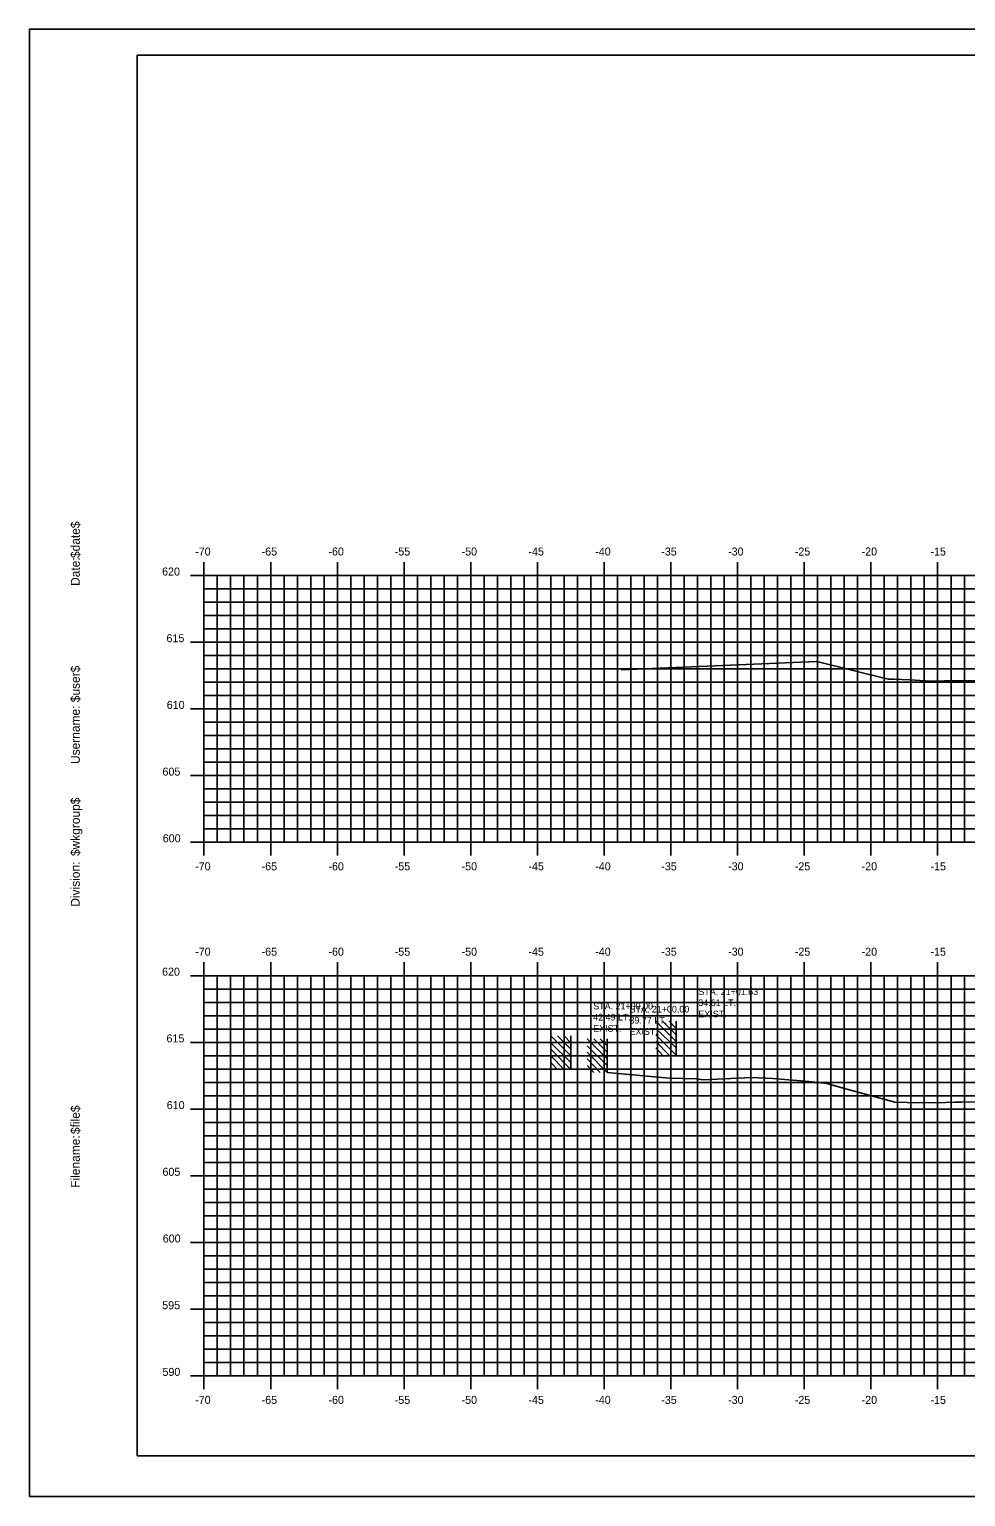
# Model space of a CAD drawing. Extents: x 1048806 to 1048976, y 780904 to 781014.
# Drawn here: x 1048805.9 to 1048876.1, y 780904.1 to 781014.1 of the extents above; entities that cross this region are included whole.
import ezdxf

# ---------------------------------------------------------------- set-up
doc = ezdxf.new("R2010")
doc.units = 0
for name, color, linetype in [('D_Text_Monospaced', 7, 'Continuous'), ('Default', 7, 'Continuous'), ('H_V ANNOTATION', 7, 'Continuous'), ('MAJOR', 7, 'Continuous'), ('MINOR', 7, 'Continuous'), ('S_Buildings', 7, 'Continuous'), ('S_Buildings_SillElevation', 7, 'Continuous'), ('S_Roadway_Centerline', 7, 'Continuous')]:
    doc.layers.add(name, color=color, linetype=linetype)

msp = doc.modelspace()

# ---------------------------------------------------------------- linework, layer by layer
at = {"layer": 'Default'}
for p, q in [((1048973.98, 781012.11), (1048813.98, 781012.11)), ((1048813.98, 781012.11), (1048813.98, 780907.11)), ((1048813.98, 780907.11), (1048973.98, 780907.11))]:
    msp.add_line(p, q, dxfattribs=at)
msp.add_lwpolyline([(1048805.89, 780904.06), (1048975.89, 780904.06), (1048975.89, 781014.06), (1048805.89, 781014.06)], close=True, dxfattribs=at)
at = {"layer": 'MAJOR'}
for p, q in [((1048818.98, 780974.12), (1048818.98, 780973.11)), ((1048823.98, 780974.12), (1048823.98, 780973.11)), ((1048828.98, 780974.12), (1048828.98, 780973.11)), ((1048833.98, 780974.12), (1048833.98, 780973.11)), ((1048838.98, 780974.12), (1048838.98, 780973.11)), ((1048843.98, 780974.12), (1048843.98, 780973.11)), ((1048848.98, 780974.12), (1048848.98, 780973.11)), ((1048853.98, 780974.12), (1048853.98, 780973.11)), ((1048858.98, 780974.12), (1048858.98, 780973.11)), ((1048863.98, 780974.12), (1048863.98, 780973.11)), ((1048868.98, 780974.12), (1048868.98, 780973.11)), ((1048873.98, 780974.12), (1048873.98, 780973.11)), ((1048817.98, 780973.11), (1048818.98, 780973.11)), ((1048818.98, 780973.11), (1048958.98, 780973.11)), ((1048818.98, 780953.11), (1048818.98, 780973.11)), ((1048818.98, 780953.11), (1048818.98, 780973.11)), ((1048818.98, 780973.11), (1048958.98, 780973.11)), ((1048823.98, 780953.11), (1048823.98, 780973.11)), ((1048828.98, 780953.11), (1048828.98, 780973.11)), ((1048833.98, 780953.11), (1048833.98, 780973.11)), ((1048838.98, 780953.11), (1048838.98, 780973.11)), ((1048843.98, 780953.11), (1048843.98, 780973.11)), ((1048848.98, 780953.11), (1048848.98, 780973.11)), ((1048853.98, 780953.11), (1048853.98, 780973.11)), ((1048858.98, 780953.11), (1048858.98, 780973.11)), ((1048863.98, 780953.11), (1048863.98, 780973.11)), ((1048868.98, 780953.11), (1048868.98, 780973.11)), ((1048873.98, 780953.11), (1048873.98, 780973.11)), ((1048817.98, 780968.11), (1048818.98, 780968.11)), ((1048818.98, 780968.11), (1048958.98, 780968.11)), ((1048817.98, 780963.11), (1048818.98, 780963.11)), ((1048818.98, 780963.11), (1048958.98, 780963.11)), ((1048817.98, 780958.11), (1048818.98, 780958.11)), ((1048818.98, 780958.11), (1048958.98, 780958.11)), ((1048817.98, 780953.11), (1048818.98, 780953.11)), ((1048818.98, 780953.11), (1048958.98, 780953.11)), ((1048818.98, 780953.11), (1048958.98, 780953.11)), ((1048818.98, 780952.11), (1048818.98, 780953.11)), ((1048823.98, 780952.11), (1048823.98, 780953.11)), ((1048828.98, 780952.11), (1048828.98, 780953.11)), ((1048833.98, 780952.11), (1048833.98, 780953.11)), ((1048838.98, 780952.11), (1048838.98, 780953.11)), ((1048843.98, 780952.11), (1048843.98, 780953.11)), ((1048848.98, 780952.11), (1048848.98, 780953.11)), ((1048853.98, 780952.11), (1048853.98, 780953.11)), ((1048858.98, 780952.11), (1048858.98, 780953.11)), ((1048863.98, 780952.11), (1048863.98, 780953.11)), ((1048868.98, 780952.11), (1048868.98, 780953.11)), ((1048873.98, 780952.11), (1048873.98, 780953.11)), ((1048818.98, 780944.12), (1048818.98, 780943.11)), ((1048823.98, 780944.12), (1048823.98, 780943.11)), ((1048828.98, 780944.12), (1048828.98, 780943.11)), ((1048833.98, 780944.12), (1048833.98, 780943.11)), ((1048838.98, 780944.12), (1048838.98, 780943.11)), ((1048843.98, 780944.12), (1048843.98, 780943.11)), ((1048848.98, 780944.12), (1048848.98, 780943.11)), ((1048853.98, 780944.12), (1048853.98, 780943.11)), ((1048858.98, 780944.12), (1048858.98, 780943.11)), ((1048863.98, 780944.12), (1048863.98, 780943.11)), ((1048868.98, 780944.12), (1048868.98, 780943.11)), ((1048873.98, 780944.12), (1048873.98, 780943.11)), ((1048817.98, 780943.11), (1048818.98, 780943.11)), ((1048818.98, 780943.11), (1048958.98, 780943.11)), ((1048818.98, 780913.11), (1048818.98, 780943.11)), ((1048818.98, 780913.11), (1048818.98, 780943.11)), ((1048818.98, 780943.11), (1048958.98, 780943.11)), ((1048823.98, 780913.11), (1048823.98, 780943.11)), ((1048828.98, 780913.11), (1048828.98, 780943.11)), ((1048833.98, 780913.11), (1048833.98, 780943.11)), ((1048838.98, 780913.11), (1048838.98, 780943.11)), ((1048843.98, 780913.11), (1048843.98, 780943.11)), ((1048848.98, 780913.11), (1048848.98, 780943.11)), ((1048853.98, 780913.11), (1048853.98, 780943.11)), ((1048858.98, 780913.11), (1048858.98, 780943.11)), ((1048863.98, 780913.11), (1048863.98, 780943.11)), ((1048868.98, 780913.11), (1048868.98, 780943.11)), ((1048873.98, 780913.11), (1048873.98, 780943.11)), ((1048817.98, 780938.11), (1048818.98, 780938.11)), ((1048818.98, 780938.11), (1048958.98, 780938.11)), ((1048817.98, 780933.11), (1048818.98, 780933.11)), ((1048818.98, 780933.11), (1048958.98, 780933.11)), ((1048817.98, 780928.11), (1048818.98, 780928.11)), ((1048818.98, 780928.11), (1048958.98, 780928.11)), ((1048817.98, 780923.11), (1048818.98, 780923.11)), ((1048818.98, 780923.11), (1048958.98, 780923.11)), ((1048817.98, 780918.11), (1048818.98, 780918.11)), ((1048818.98, 780918.11), (1048958.98, 780918.11)), ((1048817.98, 780913.11), (1048818.98, 780913.11)), ((1048818.98, 780913.11), (1048958.98, 780913.11)), ((1048818.98, 780913.11), (1048958.98, 780913.11)), ((1048818.98, 780912.11), (1048818.98, 780913.11)), ((1048823.98, 780912.11), (1048823.98, 780913.11)), ((1048828.98, 780912.11), (1048828.98, 780913.11)), ((1048833.98, 780912.11), (1048833.98, 780913.11)), ((1048838.98, 780912.11), (1048838.98, 780913.11)), ((1048843.98, 780912.11), (1048843.98, 780913.11)), ((1048848.98, 780912.11), (1048848.98, 780913.11)), ((1048853.98, 780912.11), (1048853.98, 780913.11)), ((1048858.98, 780912.11), (1048858.98, 780913.11)), ((1048863.98, 780912.11), (1048863.98, 780913.11)), ((1048868.98, 780912.11), (1048868.98, 780913.11)), ((1048873.98, 780912.11), (1048873.98, 780913.11))]:
    msp.add_line(p, q, dxfattribs=at)
at = {"layer": 'MINOR'}
for p, q in [((1048819.98, 780953.11), (1048819.98, 780973.11)), ((1048820.98, 780953.11), (1048820.98, 780973.11)), ((1048821.98, 780953.11), (1048821.98, 780973.11)), ((1048822.98, 780953.11), (1048822.98, 780973.11)), ((1048824.98, 780953.11), (1048824.98, 780973.11)), ((1048825.98, 780953.11), (1048825.98, 780973.11)), ((1048826.98, 780953.11), (1048826.98, 780973.11)), ((1048827.98, 780953.11), (1048827.98, 780973.11)), ((1048829.98, 780953.11), (1048829.98, 780973.11)), ((1048830.98, 780953.11), (1048830.98, 780973.11)), ((1048831.98, 780953.11), (1048831.98, 780973.11)), ((1048832.98, 780953.11), (1048832.98, 780973.11)), ((1048834.98, 780953.11), (1048834.98, 780973.11)), ((1048835.98, 780953.11), (1048835.98, 780973.11)), ((1048836.98, 780953.11), (1048836.98, 780973.11)), ((1048837.98, 780953.11), (1048837.98, 780973.11)), ((1048839.98, 780953.11), (1048839.98, 780973.11)), ((1048840.98, 780953.11), (1048840.98, 780973.11)), ((1048841.98, 780953.11), (1048841.98, 780973.11)), ((1048842.98, 780953.11), (1048842.98, 780973.11)), ((1048844.98, 780953.11), (1048844.98, 780973.11)), ((1048845.98, 780953.11), (1048845.98, 780973.11)), ((1048846.98, 780953.11), (1048846.98, 780973.11)), ((1048847.98, 780953.11), (1048847.98, 780973.11)), ((1048849.98, 780953.11), (1048849.98, 780973.11)), ((1048850.98, 780953.11), (1048850.98, 780973.11)), ((1048851.98, 780953.11), (1048851.98, 780973.11)), ((1048852.98, 780953.11), (1048852.98, 780973.11)), ((1048854.98, 780953.11), (1048854.98, 780973.11)), ((1048855.98, 780953.11), (1048855.98, 780973.11)), ((1048856.98, 780953.11), (1048856.98, 780973.11)), ((1048857.98, 780953.11), (1048857.98, 780973.11)), ((1048859.98, 780953.11), (1048859.98, 780973.11)), ((1048860.98, 780953.11), (1048860.98, 780973.11)), ((1048861.98, 780953.11), (1048861.98, 780973.11)), ((1048862.98, 780953.11), (1048862.98, 780973.11)), ((1048864.98, 780953.11), (1048864.98, 780973.11)), ((1048865.98, 780953.11), (1048865.98, 780973.11)), ((1048866.98, 780953.11), (1048866.98, 780973.11)), ((1048867.98, 780953.11), (1048867.98, 780973.11)), ((1048869.98, 780953.11), (1048869.98, 780973.11)), ((1048870.98, 780953.11), (1048870.98, 780973.11)), ((1048871.98, 780953.11), (1048871.98, 780973.11)), ((1048872.98, 780953.11), (1048872.98, 780973.11)), ((1048874.98, 780953.11), (1048874.98, 780973.11)), ((1048875.98, 780953.11), (1048875.98, 780973.11)), ((1048818.98, 780972.11), (1048958.98, 780972.11)), ((1048818.98, 780972.11), (1048819.98, 780972.11)), ((1048818.98, 780971.11), (1048958.98, 780971.11)), ((1048818.98, 780971.11), (1048819.98, 780971.11)), ((1048818.98, 780970.11), (1048958.98, 780970.11)), ((1048818.98, 780970.11), (1048819.98, 780970.11)), ((1048818.98, 780969.11), (1048958.98, 780969.11)), ((1048818.98, 780969.11), (1048819.98, 780969.11)), ((1048818.98, 780967.11), (1048958.98, 780967.11)), ((1048818.98, 780967.11), (1048819.98, 780967.11)), ((1048818.98, 780966.11), (1048958.98, 780966.11)), ((1048818.98, 780966.11), (1048819.98, 780966.11)), ((1048818.98, 780965.11), (1048958.98, 780965.11)), ((1048818.98, 780965.11), (1048819.98, 780965.11)), ((1048818.98, 780964.11), (1048958.98, 780964.11)), ((1048818.98, 780964.11), (1048819.98, 780964.11)), ((1048818.98, 780962.11), (1048958.98, 780962.11)), ((1048818.98, 780962.11), (1048819.98, 780962.11)), ((1048818.98, 780961.11), (1048958.98, 780961.11)), ((1048818.98, 780961.11), (1048819.98, 780961.11)), ((1048818.98, 780960.11), (1048958.98, 780960.11)), ((1048818.98, 780960.11), (1048819.98, 780960.11)), ((1048818.98, 780959.11), (1048958.98, 780959.11)), ((1048818.98, 780959.11), (1048819.98, 780959.11)), ((1048818.98, 780957.11), (1048958.98, 780957.11)), ((1048818.98, 780957.11), (1048819.98, 780957.11)), ((1048818.98, 780956.11), (1048958.98, 780956.11)), ((1048818.98, 780956.11), (1048819.98, 780956.11)), ((1048818.98, 780955.11), (1048958.98, 780955.11)), ((1048818.98, 780955.11), (1048819.98, 780955.11)), ((1048818.98, 780954.11), (1048958.98, 780954.11)), ((1048818.98, 780954.11), (1048819.98, 780954.11)), ((1048819.98, 780913.11), (1048819.98, 780943.11)), ((1048820.98, 780913.11), (1048820.98, 780943.11)), ((1048821.98, 780913.11), (1048821.98, 780943.11)), ((1048822.98, 780913.11), (1048822.98, 780943.11)), ((1048824.98, 780913.11), (1048824.98, 780943.11)), ((1048825.98, 780913.11), (1048825.98, 780943.11)), ((1048826.98, 780913.11), (1048826.98, 780943.11)), ((1048827.98, 780913.11), (1048827.98, 780943.11)), ((1048829.98, 780913.11), (1048829.98, 780943.11)), ((1048830.98, 780913.11), (1048830.98, 780943.11)), ((1048831.98, 780913.11), (1048831.98, 780943.11)), ((1048832.98, 780913.11), (1048832.98, 780943.11)), ((1048834.98, 780913.11), (1048834.98, 780943.11)), ((1048835.98, 780913.11), (1048835.98, 780943.11)), ((1048836.98, 780913.11), (1048836.98, 780943.11)), ((1048837.98, 780913.11), (1048837.98, 780943.11)), ((1048839.98, 780913.11), (1048839.98, 780943.11)), ((1048840.98, 780913.11), (1048840.98, 780943.11)), ((1048841.98, 780913.11), (1048841.98, 780943.11)), ((1048842.98, 780913.11), (1048842.98, 780943.11)), ((1048844.98, 780913.11), (1048844.98, 780943.11)), ((1048845.98, 780913.11), (1048845.98, 780943.11)), ((1048846.98, 780913.11), (1048846.98, 780943.11)), ((1048847.98, 780913.11), (1048847.98, 780943.11)), ((1048849.98, 780913.11), (1048849.98, 780943.11)), ((1048850.98, 780913.11), (1048850.98, 780943.11)), ((1048851.98, 780913.11), (1048851.98, 780943.11)), ((1048852.98, 780913.11), (1048852.98, 780943.11)), ((1048854.98, 780913.11), (1048854.98, 780943.11)), ((1048855.98, 780913.11), (1048855.98, 780943.11)), ((1048856.98, 780913.11), (1048856.98, 780943.11)), ((1048857.98, 780913.11), (1048857.98, 780943.11)), ((1048859.98, 780913.11), (1048859.98, 780943.11)), ((1048860.98, 780913.11), (1048860.98, 780943.11)), ((1048861.98, 780913.11), (1048861.98, 780943.11)), ((1048862.98, 780913.11), (1048862.98, 780943.11)), ((1048864.98, 780913.11), (1048864.98, 780943.11)), ((1048865.98, 780913.11), (1048865.98, 780943.11)), ((1048866.98, 780913.11), (1048866.98, 780943.11)), ((1048867.98, 780913.11), (1048867.98, 780943.11)), ((1048869.98, 780913.11), (1048869.98, 780943.11)), ((1048870.98, 780913.11), (1048870.98, 780943.11)), ((1048871.98, 780913.11), (1048871.98, 780943.11)), ((1048872.98, 780913.11), (1048872.98, 780943.11)), ((1048874.98, 780913.11), (1048874.98, 780943.11)), ((1048875.98, 780913.11), (1048875.98, 780943.11)), ((1048818.98, 780942.11), (1048958.98, 780942.11)), ((1048818.98, 780942.11), (1048819.98, 780942.11)), ((1048818.98, 780941.11), (1048958.98, 780941.11)), ((1048818.98, 780941.11), (1048819.98, 780941.11)), ((1048818.98, 780940.11), (1048958.98, 780940.11)), ((1048818.98, 780940.11), (1048819.98, 780940.11)), ((1048818.98, 780939.11), (1048958.98, 780939.11)), ((1048818.98, 780939.11), (1048819.98, 780939.11)), ((1048818.98, 780937.11), (1048958.98, 780937.11)), ((1048818.98, 780937.11), (1048819.98, 780937.11)), ((1048818.98, 780936.11), (1048958.98, 780936.11)), ((1048818.98, 780936.11), (1048819.98, 780936.11)), ((1048818.98, 780935.11), (1048958.98, 780935.11)), ((1048818.98, 780935.11), (1048819.98, 780935.11)), ((1048818.98, 780934.11), (1048958.98, 780934.11)), ((1048818.98, 780934.11), (1048819.98, 780934.11)), ((1048818.98, 780932.11), (1048958.98, 780932.11)), ((1048818.98, 780932.11), (1048819.98, 780932.11)), ((1048818.98, 780931.11), (1048958.98, 780931.11)), ((1048818.98, 780931.11), (1048819.98, 780931.11)), ((1048818.98, 780930.11), (1048958.98, 780930.11)), ((1048818.98, 780930.11), (1048819.98, 780930.11)), ((1048818.98, 780929.11), (1048958.98, 780929.11)), ((1048818.98, 780929.11), (1048819.98, 780929.11)), ((1048818.98, 780927.11), (1048958.98, 780927.11)), ((1048818.98, 780927.11), (1048819.98, 780927.11)), ((1048818.98, 780926.11), (1048958.98, 780926.11)), ((1048818.98, 780926.11), (1048819.98, 780926.11)), ((1048818.98, 780925.11), (1048958.98, 780925.11)), ((1048818.98, 780925.11), (1048819.98, 780925.11)), ((1048818.98, 780924.11), (1048958.98, 780924.11)), ((1048818.98, 780924.11), (1048819.98, 780924.11)), ((1048818.98, 780922.11), (1048958.98, 780922.11)), ((1048818.98, 780922.11), (1048819.98, 780922.11)), ((1048818.98, 780921.11), (1048958.98, 780921.11)), ((1048818.98, 780921.11), (1048819.98, 780921.11)), ((1048818.98, 780920.11), (1048958.98, 780920.11)), ((1048818.98, 780920.11), (1048819.98, 780920.11)), ((1048818.98, 780919.11), (1048958.98, 780919.11)), ((1048818.98, 780919.11), (1048819.98, 780919.11)), ((1048818.98, 780917.11), (1048958.98, 780917.11)), ((1048818.98, 780917.11), (1048819.98, 780917.11)), ((1048818.98, 780916.11), (1048958.98, 780916.11)), ((1048818.98, 780916.11), (1048819.98, 780916.11)), ((1048818.98, 780915.11), (1048958.98, 780915.11)), ((1048818.98, 780915.11), (1048819.98, 780915.11)), ((1048818.98, 780914.11), (1048958.98, 780914.11)), ((1048818.98, 780914.11), (1048819.98, 780914.11))]:
    msp.add_line(p, q, dxfattribs=at)
at = {"layer": 'S_Buildings'}
for p, q in [((1048846.49, 780937.1), (1048844.98, 780938.61)), ((1048846.49, 780937.59), (1048845.48, 780938.61)), ((1048846.49, 780938.08), (1048845.97, 780938.61)), ((1048846.49, 780936.08), (1048846.49, 780938.61)), ((1048846.49, 780936.61), (1048844.98, 780938.08)), ((1048846.49, 780936.08), (1048844.98, 780937.59)), ((1048849.21, 780936.87), (1048847.71, 780938.38)), ((1048849.21, 780936.38), (1048847.71, 780937.86)), ((1048849.21, 780935.86), (1048847.71, 780937.37)), ((1048849.21, 780937.37), (1048848.2, 780938.38)), ((1048849.21, 780937.86), (1048848.69, 780938.38)), ((1048849.21, 780935.86), (1048849.21, 780938.38)), ((1048845.97, 780936.08), (1048844.98, 780937.1)), ((1048845.48, 780936.08), (1048844.98, 780936.61)), ((1048848.69, 780935.86), (1048847.71, 780936.87)), ((1048848.2, 780935.86), (1048847.71, 780936.38))]:
    msp.add_line(p, q, dxfattribs=at)
at = {"layer": 'S_Buildings_SillElevation'}
for p, q in [((1048854.37, 780938.18), (1048852.86, 780939.69)), ((1048854.37, 780938.67), (1048853.35, 780939.69)), ((1048854.37, 780939.16), (1048853.85, 780939.69)), ((1048854.37, 780937.16), (1048854.37, 780939.69)), ((1048854.37, 780937.69), (1048852.86, 780939.16)), ((1048854.37, 780937.16), (1048852.86, 780938.67)), ((1048853.85, 780937.16), (1048852.86, 780938.18)), ((1048853.35, 780937.16), (1048852.86, 780937.69))]:
    msp.add_line(p, q, dxfattribs=at)
at = {"layer": 'S_Roadway_Centerline'}
for points in [[(1048850.25, 780966.04), (1048864.9, 780966.66), (1048864.94, 780966.66), (1048865.01, 780966.64), (1048870.28, 780965.34), (1048870.73, 780965.35), (1048871.9, 780965.3), (1048873.47, 780965.19), (1048874.46, 780965.21), (1048875.46, 780965.21), (1048876.87, 780965.25)], [(1048849.21, 780935.86), (1048853.86, 780935.44), (1048855.89, 780935.38), (1048856.42, 780935.31), (1048860.02, 780935.47), (1048861.62, 780935.4), (1048864.32, 780935.18), (1048865.66, 780935.04), (1048867.18, 780934.6), (1048870.76, 780933.63), (1048871.69, 780933.61), (1048873.51, 780933.57), (1048874.58, 780933.61), (1048875.27, 780933.63), (1048875.74, 780933.64), (1048878.49, 780933.65)]]:
    msp.add_lwpolyline(points, dxfattribs=at)

# ---------------------------------------------------------------- texts
at = {"layer": 'D_Text_Monospaced'}
for s, p in [('STA. 21+01.63', (1048856.04, 780941.66)), ('STA. 21+00.00', (1048848.16, 780940.58)), ('STA. 21+00.00', (1048850.88, 780940.35)), ('34.61 LT.', (1048856.04, 780940.83)), ('42.49 LT.', (1048848.16, 780939.75)), ('39.77 LT.', (1048850.88, 780939.52)), ('EXIST. ', (1048856.04, 780939.99)), ('EXIST. ', (1048848.16, 780938.91)), ('EXIST. ', (1048850.88, 780938.68))]:
    msp.add_text(s, height=0.5, dxfattribs=at).set_placement(p)
at = {"layer": 'Default'}
for s, p in [('$date$', (1048809.67, 780974.42)), ('Date:', (1048809.67, 780972.33)), ('$user$', (1048809.67, 780963.61)), ('Username:', (1048809.67, 780958.98)), ('$wkgroup$', (1048809.67, 780952.08)), ('Division:', (1048809.67, 780948.28)), ('$file$', (1048809.67, 780931.24)), ('Filename:', (1048809.67, 780927.21))]:
    msp.add_text(s, height=0.67, rotation=90, dxfattribs=at).set_placement(p)
at = {"layer": 'H_V ANNOTATION'}
for s, p in [('-70', (1048818.32, 780974.61)), ('-65', (1048823.3, 780974.61)), ('-60', (1048828.31, 780974.61)), ('-55', (1048833.28, 780974.61)), ('-50', (1048838.29, 780974.61)), ('-45', (1048843.3, 780974.61)), ('-40', (1048848.31, 780974.61)), ('-35', (1048853.26, 780974.61)), ('-30', (1048858.27, 780974.61)), ('-25', (1048863.27, 780974.61)), ('-20', (1048868.28, 780974.61)), ('-15', (1048873.44, 780974.61)), ('620', (1048815.84, 780973.11)), ('615', (1048816.17, 780968.11)), ('610', (1048816.19, 780963.11)), ('605', (1048815.87, 780958.11)), ('600', (1048815.89, 780953.11)), ('-70', (1048818.32, 780951.01)), ('-65', (1048823.3, 780951.01)), ('-60', (1048828.31, 780951.01)), ('-55', (1048833.28, 780951.01)), ('-50', (1048838.29, 780951.01)), ('-45', (1048843.3, 780951.01)), ('-40', (1048848.31, 780951.01)), ('-35', (1048853.26, 780951.01)), ('-30', (1048858.27, 780951.01)), ('-25', (1048863.27, 780951.01)), ('-20', (1048868.28, 780951.01)), ('-15', (1048873.44, 780951.01)), ('-70', (1048818.32, 780944.61)), ('-65', (1048823.3, 780944.61)), ('-60', (1048828.31, 780944.61)), ('-55', (1048833.28, 780944.61)), ('-50', (1048838.29, 780944.61)), ('-45', (1048843.3, 780944.61)), ('-40', (1048848.31, 780944.61)), ('-35', (1048853.26, 780944.61)), ('-30', (1048858.27, 780944.61)), ('-25', (1048863.27, 780944.61)), ('-20', (1048868.28, 780944.61)), ('-15', (1048873.44, 780944.61)), ('620', (1048815.84, 780943.11)), ('615', (1048816.17, 780938.11)), ('610', (1048816.19, 780933.11)), ('605', (1048815.87, 780928.11)), ('600', (1048815.89, 780923.11)), ('595', (1048815.85, 780918.11)), ('590', (1048815.87, 780913.11)), ('-70', (1048818.32, 780911.01)), ('-65', (1048823.3, 780911.01)), ('-60', (1048828.31, 780911.01)), ('-55', (1048833.28, 780911.01)), ('-50', (1048838.29, 780911.01)), ('-45', (1048843.3, 780911.01)), ('-40', (1048848.31, 780911.01)), ('-35', (1048853.26, 780911.01)), ('-30', (1048858.27, 780911.01)), ('-25', (1048863.27, 780911.01)), ('-20', (1048868.28, 780911.01)), ('-15', (1048873.44, 780911.01))]:
    msp.add_text(s, height=0.6, dxfattribs=at).set_placement(p)
at = {"layer": 'MAJOR'}
for p in [(1048818.98, 780953.11), (1048818.98, 780913.11)]:
    msp.add_text('-', height=0.006, dxfattribs=at).set_placement(p)

doc.saveas('drawing.dxf')
